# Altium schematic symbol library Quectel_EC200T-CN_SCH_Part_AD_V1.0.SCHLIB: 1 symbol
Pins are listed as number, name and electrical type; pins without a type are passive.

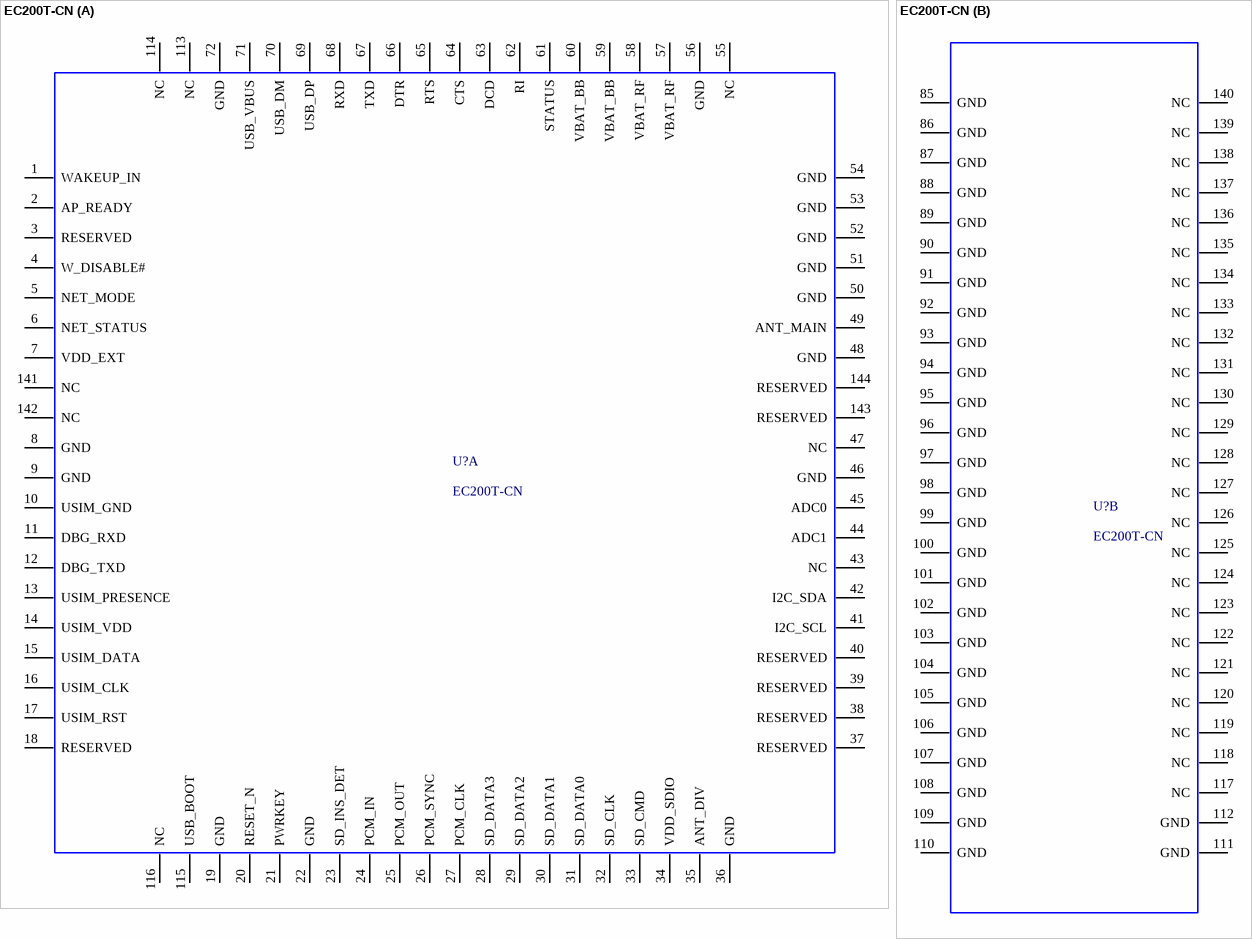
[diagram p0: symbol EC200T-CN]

## EC200T-CN
designator U?
Part Description: EC200T-CN Moudle 144PIN 29x32mm; Manufacturer: Quectel; Geometry.Height: 2.6mm
footprint EC200T-CN
part A pins: 1 WAKEUP_IN, 2 AP_READY, 3 RESERVED, 4 W_DISABLE#, 5 NET_MODE, 6 NET_STATUS, 7 VDD_EXT, 8 GND, 9 GND, 10 USIM_GND, 11 DBG_RXD, 12 DBG_TXD, 13 USIM_PRESENCE, 14 USIM_VDD, 15 USIM_DATA, 16 USIM_CLK, 17 USIM_RST, 18 RESERVED, 19 GND, 20 RESET_N, 21 PWRKEY, 22 GND, 23 SD_INS_DET, 24 PCM_IN, 25 PCM_OUT, 26 PCM_SYNC, 27 PCM_CLK, 28 SD_DATA3, 29 SD_DATA2, 30 SD_DATA1, 31 SD_DATA0, 32 SD_CLK, 33 SD_CMD, 34 VDD_SDIO, 35 ANT_DIV, 36 GND, 37 RESERVED, 38 RESERVED, 39 RESERVED, 40 RESERVED, 41 I2C_SCL, 42 I2C_SDA, 43 NC, 44 ADC1, 45 ADC0, 46 GND, 47 NC, 48 GND, 49 ANT_MAIN, 50 GND, 51 GND, 52 GND, 53 GND, 54 GND, 55 NC, 56 GND, 57 VBAT_RF, 58 VBAT_RF, 59 VBAT_BB, 60 VBAT_BB, 61 STATUS, 62 RI, 63 DCD, 64 CTS, 65 RTS, 66 DTR, 67 TXD, 68 RXD, 69 USB_DP, 70 USB_DM, 71 USB_VBUS, 72 GND, 113 NC, 114 NC, 115 USB_BOOT, 116 NC, 141 NC, 142 NC, 143 RESERVED, 144 RESERVED
part B pins: 85 GND, 86 GND, 87 GND, 88 GND, 89 GND, 90 GND, 91 GND, 92 GND, 93 GND, 94 GND, 95 GND, 96 GND, 97 GND, 98 GND, 99 GND, 100 GND, 101 GND, 102 GND, 103 GND, 104 GND, 105 GND, 106 GND, 107 GND, 108 GND, 109 GND, 110 GND, 111 GND, 112 GND, 117 NC, 118 NC, 119 NC, 120 NC, 121 NC, 122 NC, 123 NC, 124 NC, 125 NC, 126 NC, 127 NC, 128 NC, 129 NC, 130 NC, 131 NC, 132 NC, 133 NC, 134 NC, 135 NC, 136 NC, 137 NC, 138 NC, 139 NC, 140 NC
